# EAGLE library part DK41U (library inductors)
FILTER
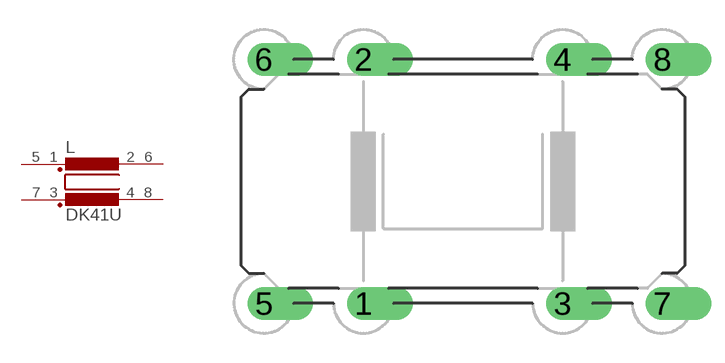
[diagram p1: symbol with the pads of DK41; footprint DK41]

Designator prefix L

## DK41U  [DK41]
1  1  pas
2  2  pas
3  3  pas
4  4  pas
5  5  pas
6  6  pas
7  7  pas
8  8  pas

## Footprint DK41 (pad centres in mm)
FILTER manufacturer Vogt
drill 1.118 offset: 1 -5.08,-6.223; 2 -5.08,6.223; 3 5.08,-6.223; 4 5.08,6.223; 5 -10.16,-6.223; 6 -10.16,6.223; 7 10.16,-6.223; 8 10.16,6.223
